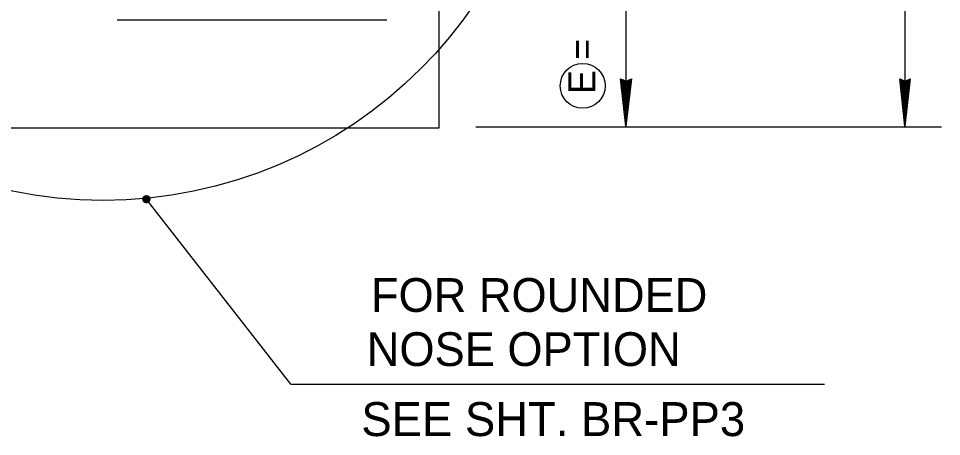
# Model space of a CAD drawing. Extents: x 1.6 to 6.29, y 2.8 to 7.08.
# Drawn here: x 3.4141 to 3.8397, y 6.1975 to 6.3905 of the extents above; entities that cross this region are included whole.
import ezdxf

# ---------------------------------------------------------------- set-up
doc = ezdxf.new("R2010")
doc.units = 0
doc.layers.add('Level 1', color=7, linetype='Continuous')
doc.layers.add('Level 5', color=7, linetype='Continuous')

msp = doc.modelspace()

# ---------------------------------------------------------------- linework, layer by layer
at = {"layer": 'Level 1'}
for p, q in [((3.60783, 6.74125), (3.60783, 6.33992)), ((3.69417, 6.74017), (3.69417, 6.34283)), ((3.82275, 6.741), (3.82275, 6.34175)), ((3.45958, 6.38992), (3.58392, 6.38992)), ((3.69417, 6.34075), (3.69167, 6.36267)), ((3.69167, 6.36267), (3.69425, 6.36158)), ((3.69417, 6.36267), (3.69417, 6.34075)), ((3.69675, 6.36267), (3.69417, 6.34075)), ((3.69425, 6.36158), (3.69675, 6.36267)), ((3.82275, 6.34075), (3.82042, 6.36267)), ((3.82042, 6.36267), (3.82283, 6.36158)), ((3.82275, 6.36267), (3.82275, 6.34075)), ((3.82525, 6.36267), (3.82275, 6.34075)), ((3.82283, 6.36158), (3.82525, 6.36267)), ((3.69217, 6.36233), (3.69383, 6.34708)), ((3.69325, 6.36183), (3.69233, 6.36233)), ((3.69242, 6.36233), (3.694, 6.34708)), ((3.69267, 6.36233), (3.69425, 6.34717)), ((3.69292, 6.36233), (3.69458, 6.34725)), ((3.69417, 6.36133), (3.69325, 6.36183)), ((3.6945, 6.35017), (3.69325, 6.36167)), ((3.69325, 6.36167), (3.6945, 6.36117)), ((3.69367, 6.35625), (3.69367, 6.36158)), ((3.69367, 6.36158), (3.6945, 6.35017)), ((3.694, 6.36125), (3.69367, 6.35625)), ((3.69408, 6.34383), (3.694, 6.36125)), ((3.69592, 6.36233), (3.69417, 6.34583)), ((3.69567, 6.36108), (3.69417, 6.36133)), ((3.696, 6.36233), (3.69425, 6.34583)), ((3.69633, 6.36233), (3.6945, 6.34583)), ((3.6945, 6.36117), (3.69592, 6.36208)), ((3.6965, 6.36233), (3.69458, 6.34583)), ((3.69642, 6.36233), (3.69458, 6.34583)), ((3.69458, 6.36125), (3.69458, 6.35158)), ((3.69458, 6.35333), (3.69458, 6.36125)), ((3.69458, 6.36125), (3.69483, 6.35492)), ((3.69525, 6.36175), (3.69483, 6.35408)), ((3.69567, 6.36167), (3.69483, 6.36117)), ((3.69483, 6.35492), (3.69483, 6.36158)), ((3.69483, 6.36158), (3.695, 6.35692)), ((3.69483, 6.36117), (3.69492, 6.36075)), ((3.69492, 6.36075), (3.69567, 6.36108)), ((3.695, 6.35692), (3.69525, 6.36175)), ((3.69592, 6.36208), (3.69567, 6.36167)), ((3.82067, 6.36233), (3.82242, 6.34708)), ((3.82167, 6.36183), (3.82075, 6.36233)), ((3.82092, 6.36233), (3.82258, 6.34708)), ((3.82117, 6.36233), (3.82283, 6.34717)), ((3.82142, 6.36233), (3.82325, 6.34725)), ((3.82275, 6.36133), (3.82167, 6.36183)), ((3.823, 6.35017), (3.82167, 6.36167)), ((3.82167, 6.36167), (3.823, 6.36117)), ((3.82225, 6.35625), (3.82225, 6.36158)), ((3.82225, 6.36158), (3.823, 6.35017)), ((3.82258, 6.36125), (3.82225, 6.35625)), ((3.82267, 6.34383), (3.82258, 6.36125)), ((3.82458, 6.36233), (3.82275, 6.34583)), ((3.82433, 6.36108), (3.82275, 6.36133)), ((3.82467, 6.36233), (3.82283, 6.34583)), ((3.82492, 6.36233), (3.823, 6.34583)), ((3.823, 6.36117), (3.82467, 6.36208)), ((3.825, 6.36233), (3.82325, 6.34583)), ((3.82492, 6.36233), (3.82325, 6.34583)), ((3.82325, 6.36125), (3.82325, 6.35158)), ((3.82325, 6.35333), (3.82325, 6.36125)), ((3.82325, 6.36125), (3.82358, 6.35492)), ((3.82392, 6.36175), (3.82342, 6.35408)), ((3.82425, 6.36167), (3.82342, 6.36117)), ((3.82342, 6.36117), (3.82358, 6.36075)), ((3.82358, 6.35492), (3.82358, 6.36158)), ((3.82358, 6.36158), (3.82367, 6.35692)), ((3.82358, 6.36075), (3.82433, 6.36108)), ((3.82367, 6.35692), (3.82392, 6.36175)), ((3.82467, 6.36208), (3.82425, 6.36167)), ((3.69483, 6.35408), (3.69433, 6.34442)), ((3.82342, 6.35408), (3.82292, 6.34442)), ((3.69433, 6.35158), (3.69458, 6.35333)), ((3.69458, 6.35158), (3.69433, 6.35158)), ((3.82292, 6.35158), (3.82325, 6.35333)), ((3.82325, 6.35158), (3.82292, 6.35158)), ((3.69433, 6.34442), (3.69383, 6.3465)), ((3.69383, 6.3465), (3.69408, 6.34383)), ((3.82292, 6.34442), (3.82242, 6.3465)), ((3.82242, 6.3465), (3.82267, 6.34383)), ((3.60783, 6.33992), (2.80525, 6.33992)), ((3.62492, 6.34042), (3.83967, 6.34042)), ((3.4715, 6.307), (3.47458, 6.3075)), ((3.47158, 6.30767), (3.47442, 6.30783)), ((3.47158, 6.30742), (3.47317, 6.30775)), ((3.47342, 6.30542), (3.47158, 6.30767)), ((3.474, 6.30575), (3.47158, 6.30742)), ((3.47175, 6.30783), (3.47283, 6.30875)), ((3.47183, 6.30808), (3.47175, 6.30608)), ((3.473, 6.30717), (3.47175, 6.30783)), ((3.47375, 6.30867), (3.47183, 6.30808)), ((3.47458, 6.3075), (3.47183, 6.30808)), ((3.47183, 6.30808), (3.47458, 6.30658)), ((3.47192, 6.30808), (3.47183, 6.30608)), ((3.47183, 6.3075), (3.47425, 6.307)), ((3.47183, 6.30742), (3.47425, 6.30675)), ((3.47208, 6.30808), (3.47192, 6.30608)), ((3.47192, 6.30808), (3.47433, 6.3075)), ((3.47192, 6.30808), (3.47433, 6.30767)), ((3.47192, 6.30783), (3.47433, 6.30742)), ((3.47192, 6.30775), (3.47433, 6.30717)), ((3.47192, 6.3075), (3.47425, 6.30708)), ((3.47333, 6.30875), (3.47208, 6.30575)), ((3.47208, 6.30575), (3.4725, 6.30875)), ((3.47208, 6.30833), (3.47433, 6.30783)), ((3.47217, 6.30808), (3.47208, 6.30608)), ((3.47225, 6.30808), (3.47217, 6.30608)), ((3.47233, 6.30808), (3.47225, 6.30608)), ((3.53967, 6.22175), (3.47233, 6.30808)), ((3.4725, 6.30875), (3.47342, 6.30542)), ((3.4725, 6.3055), (3.47375, 6.30867)), ((3.47258, 6.30808), (3.4725, 6.30608)), ((3.47442, 6.30783), (3.4725, 6.3055)), ((3.47267, 6.30808), (3.47258, 6.30608)), ((3.47275, 6.30808), (3.47267, 6.30608)), ((3.47283, 6.30808), (3.47275, 6.30608)), ((3.47283, 6.30875), (3.473, 6.30742)), ((3.473, 6.30808), (3.47283, 6.30608)), ((3.473, 6.30542), (3.47333, 6.30875)), ((3.47375, 6.30867), (3.473, 6.30717)), ((3.47408, 6.30842), (3.473, 6.30542)), ((3.47308, 6.30808), (3.473, 6.30608)), ((3.473, 6.30742), (3.474, 6.30575)), ((3.47317, 6.30808), (3.47308, 6.30608)), ((3.47317, 6.30775), (3.47408, 6.30842)), ((3.47333, 6.30808), (3.47317, 6.306)), ((3.47358, 6.30808), (3.47333, 6.306)), ((3.47367, 6.30808), (3.47358, 6.306)), ((3.47367, 6.30808), (3.47358, 6.306)), ((3.47375, 6.30808), (3.47367, 6.306)), ((3.47442, 6.30783), (3.47375, 6.30867)), ((3.47383, 6.30808), (3.47375, 6.306)), ((3.474, 6.30808), (3.47383, 6.306)), ((3.47408, 6.30808), (3.474, 6.306)), ((3.47408, 6.30575), (3.47408, 6.30842)), ((3.47425, 6.30808), (3.47408, 6.306)), ((3.47408, 6.30808), (3.47408, 6.306)), ((3.47442, 6.30808), (3.47433, 6.306)), ((3.47458, 6.30658), (3.47442, 6.30783)), ((3.47458, 6.30658), (3.47175, 6.30608)), ((3.47175, 6.30625), (3.47408, 6.30583)), ((3.47175, 6.30608), (3.47408, 6.30575)), ((3.47175, 6.30608), (3.473, 6.30542)), ((3.47183, 6.30717), (3.47408, 6.30658)), ((3.47183, 6.30708), (3.47408, 6.30658)), ((3.47183, 6.30683), (3.47408, 6.30633)), ((3.47183, 6.30658), (3.47408, 6.30608)), ((3.47183, 6.30633), (3.47408, 6.30592)), ((3.47183, 6.30633), (3.47408, 6.306)), ((3.47208, 6.30575), (3.473, 6.30717)), ((3.47433, 6.306), (3.47208, 6.30575)), ((3.473, 6.30717), (3.47433, 6.306)), ((3.473, 6.30542), (3.47408, 6.30575)), ((3.47408, 6.30575), (3.47458, 6.30658)), ((3.53967, 6.22175), (3.78567, 6.22175))]:
    msp.add_line(p, q, dxfattribs=at)
for centre, radius in [((3.45306, 6.51361), 0.20706), ((3.67422, 6.35938), 0.01036), ((3.47306, 6.30704), 0.00164)]:
    msp.add_circle(centre, radius, dxfattribs=at)

# ---------------------------------------------------------------- texts
at = {"layer": 'Level 5'}
msp.add_text('E =      ', height=0.0125, rotation=90, dxfattribs=at).set_placement((3.68008, 6.35558))
for s, height, p in [('FOR ROUNDED', 0.015583, (3.57658, 6.25508)), ('NOSE OPTION', 0.015583, (3.57467, 6.23008)), ('SEE SHT. BR-PP3', 0.0156665, (3.57217, 6.19775))]:
    msp.add_text(s, height=height, dxfattribs=at).set_placement(p)

doc.saveas('drawing.dxf')
